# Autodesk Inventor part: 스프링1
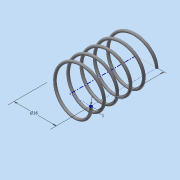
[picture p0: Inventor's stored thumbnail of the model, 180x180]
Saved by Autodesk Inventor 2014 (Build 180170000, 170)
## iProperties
Created: 2015-06
Part Number: 스프링1
Material: 강철, 연강
Document SubType Name: Modeling
Designer: MYHOME
Density: 1 g/cm^3
Appearance: 강철
Mass: 0.194555 g
Surface Area: 7.8715 cm^2
Volume: 0.194555 cm^3
Author: MYHOME
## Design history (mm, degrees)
sketch "스케치1"
  geometry: L1 (0, 0)-(8, 0); L2 (8, 0)-(8, 14.5); L3 (8, 14.5)-(0, 14.5); L4 (0, 14.5)-(0, 0); C1 r 0.5 at (8, 0)
  constraints: 8 end point, 2 parallel, 1 centre point, 1 coincident, 1 horizontal, 1 perpendicular
  dimensions: "d0" = 16 diameter of L2 L4; "d1" = 14.5 distance of L1.end L2.end (derived); "d2" = 1 diameter of C1
feature "코일1" sketch "스케치1" pitch "d3" = 10; turns "d5" = 5; dims "d4" = 14.5 (= d1), "d6" = 0, angle "d7" = 90 deg, angle "d8" = 90 deg, "d9" = 0, "d10" = 0
node "작업 평면1"
sketch "스케치2"
  geometry: L1 (-8.5, 0)-(-7.5, 0) reference; 1 further point
  constraints: 1 horizontal alignment
extrude "돌출1" cut sketch "스케치2" stored distance "d12" = 10; taper "d13" = 0 deg
node "작업 평면2"
sketch "스케치3"
  geometry: L1 (8.5, 0)-(7.5, 0) reference; 1 further point
  constraints: 1 horizontal alignment
extrude "돌출2" cut sketch "스케치3" stored distance "d15" = 10; taper "d16" = 0 deg
node "솔리드1"
node "절단 모서리 투영1"
node "절단 모서리 투영2"
other parameters: "d11" = 0, "d14" = -14.5 (= -d1)
